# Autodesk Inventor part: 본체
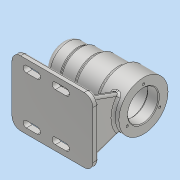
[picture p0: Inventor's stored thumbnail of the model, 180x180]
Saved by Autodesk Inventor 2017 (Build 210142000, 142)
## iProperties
Part Number: 본체
Material: 알루미늄 6061
Document SubType Name: Modeling
Designer: MRC
Density: 2.7 g/cm^3
Appearance: 알루미늄 - 평지
Mass: 694.197 g
Surface Area: 698.877 cm^2
Volume: 257.11 cm^3
Author: MRC
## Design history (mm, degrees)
sketch "스케치1"
  geometry: L1 (0, 0)-(-112, 0); L2 (0, 0)-(0, 34); L3 (0, 34)-(-32, 34); L4 (-32, 34)-(-32, 30); L5 (-32, 30)-(-66, 30); L6 (-66, 30)-(-66, 27); L7 (-66, 27)-(-88, 27); L8 (-88, 27)-(-88, 25); L9 (-88, 25)-(-112, 25); L10 (-112, 25)-(-112, 0); L11 (0, 21)-(-15, 21); L12 (-15, 21)-(-15, 24); L13 (-15, 24)-(-69, 24); L14 (-69, 24)-(-69, 21); L15 (-69, 21)-(-81, 21); L16 (-81, 21)-(-81, 17.5); L17 (-81, 17.5)-(-99, 17.5); L18 (-99, 17.5)-(-99, 16); L19 (-99, 16)-(-103, 16); L20 (-103, 16)-(-103, 10.5); L21 (-103, 10.5)-(-106, 10.5); L22 (-106, 10.5)-(-106, 0)
  constraints: 44 end point, 15 perpendicular, 3 vertical, 2 horizontal, 2 point on line, 1 parallel
  dimensions: "d0" = 112 distance of L1.start L1.end; "d1" = 24 distance between parallel lines of L8 L10; "d2" = 46 distance between parallel lines of L6 L10; "d3" = 80 distance between parallel lines of L4 L10; "d4" = 68 diameter of L3 L1; "d5" = 60 diameter of L5 L1; "d6" = 54 diameter of L7 L1; "d7" = 50 diameter of L9 L1; "d8" = 15 distance of L11.start L11.end; "d9" = 54 distance of L12.end L13.end; "d10" = 12 distance of L14.end L15.end; "d11" = 18 distance of L16.end L17.end; "d12" = 4 distance of L18.end L19.end; "d13" = 3 distance of L20.end L21.end; "d14" = 42 diameter of L11 L1; "d15" = 48 diameter of L13 L1; "d16" = 42 diameter of L15 L1; "d17" = 35 diameter of L17 L1; "d18" = 32 diameter of L19 L1; "d19" = 21 diameter of L21 L1
revolve "회전1" sketch "스케치1" stored, may be unused: angle "d20" = 90 deg
fillet "모깎기1" dims "d21" = 0.3
fillet "모깎기2" dims "d22" = 3
chamfer "모따기1" distance "d23" = 1; stored, may be unused: second distance "d24" = 2, angle "d25" = 45 deg
fillet "모깎기3" dims "d26" = 8
fillet "모깎기4" dims "d27" = 3
sketch "스케치2"
  geometry: L1 (0, 0)-(13, 22.517); L2 (0, 0)-(26, 0); C1 r 22 at (0, 0) reference; 1 further point
  constraints: 4 end point, 1 coincident, 1 equal length, 1 horizontal
  dimensions: "d28" = 26 distance of L1.start L1.end; "d29" = 60 deg angle of L2 L1
hole "구멍1" sketch "스케치2" at (13, 22.517) diameter "d30" = 3.242; stored, may be unused: countersink angle "d34" = 90 deg, drill point angle "d36" = 118 deg; dims "d31" = 8, "d32" = 4, "d33" = 2, "d35" = 11
node "작업 평면1"
sketch "스케치3"
  geometry: L1 (112, -45)-(0, -45); L2 (0, -45)-(0, 45); L3 (0, 45)-(112, 45); L4 (112, 45)-(112, -45); 2 further points
  constraints: 8 end point, 2 parallel, 1 coincident, 1 horizontal, 1 midpoint, 1 perpendicular
  dimensions: "d41" = 112 distance of L2.end L3.end; "d42" = 90 distance of L1.end L2.end
extrude "돌출1" join sketch "스케치3" distance "d43" = 8; taper "d44" = 0 deg
fillet "모깎기5" dims "d45" = 12
node "작업 평면2"
sketch "스케치4"
  geometry: L1 (56.409, 45.342)-(70, 8); L2 (9.591, 45.342)-(-4, 8); L3 (66, 8)-(78, 8) reference; L4 (-12, 8)-(0, 8) reference; L5 (78, 0)-(78, 8) reference; L6 (-12, 8)-(-12, 0) reference; L7 (-4, 8)-(70, 8); A1 r 34 centre (33, 70) between (9.591, 45.342) and (56.409, 45.342) reference; 1 further point
  constraints: 6 end point, 2 point on circle, 2 point on line, 1 horizontal
  dimensions: "d47" = 8 distance from line of L5 L1.end; "d48" = 8 distance from line of L6 L2.end; "d49" = 110 deg angle of L4 L2; "d50" = 110 deg angle of L3 L1
extrude "돌출2" join sketch "스케치4" distance "d51" = 8; taper "d52" = 0 deg
sketch "스케치5"
  geometry: L1 (-78.717, -38.552)-(-85, -62); L2 (-12, -62)-(-100, -62) reference; L3 (-8, -62)-(-8, -24.658) reference; 1 further point
  constraints: 2 end point, 1 point on line
  dimensions: "d53" = 77 distance from line of L3 L1.end; "d54" = 105 deg angle of L2 L1
feature "리브1" sketch "스케치5" dims "d55" = 1, "d56" = 8, "d57" = 0, "d58" = 0, "d59" = 1, "d60" = 1
fillet "모깎기6" dims "d61" = 3
fillet "모깎기7" dims "d62" = 3
sketch "스케치6"
  geometry: L1 (-112, 33)-(-112, -33) reference; L2 (-92, -33)-(-77, -33); L3 (-92, -37.5)-(-77, -37.5); L4 (-77, -28.5)-(-92, -28.5); L5 (-52, -33)-(-37, -33); L6 (-52, -37.5)-(-37, -37.5); L7 (-37, -28.5)-(-52, -28.5); A1 r 4.5 centre (-92, -33) between (-92, -28.5) and (-92, -37.5); A2 r 4.5 centre (-77, -33) between (-77, -37.5) and (-77, -28.5); A3 r 4.5 centre (-52, -33) between (-52, -28.5) and (-52, -37.5); A4 r 4.5 centre (-37, -33) between (-37, -37.5) and (-37, -28.5); 3 further points
  constraints: 16 end point, 8 point on circle, 8 tangent, 4 centre point, 2 midpoint, 2 parallel, 2 point on line, 1 horizontal
  dimensions: "d63" = 15 distance of L2.start L2.end; "d64" = 9 diameter of A2; "d65" = 15 distance of L5.start L5.end; "d66" = 9 diameter of A4; "d67" = 33 vertical distance of L2.start point (0, 0); "d68" = 20 distance from line of L1 L2.start; "d69" = 25 distance of L5.start L2.end
extrude "돌출3" cut sketch "스케치6" stored distance "d70" = 8; taper "d71" = 0 deg
fillet "모깎기8" dims "d72" = 3
sketch "스케치7"
  geometry: L1 (-112, 33)-(-112, -33) reference; 2 further points
  constraints: 1 horizontal alignment, 1 other
  dimensions: "d73" = 12 distance from line of L1 point (-100, 0)
feature "엠보싱1" sketch "스케치7" dims "d0" = 112, "d1" = 24, "d2" = 46, "d3" = 80, "d4" = 68, "d5" = 60, "d6" = 54, "d7" = 50, "d8" = 15, "d9" = 54, "d10" = 12, "d11" = 18, "d12" = 4, "d13" = 3, "d14" = 42, "d15" = 48, "d16" = 42, "d17" = 35, "d18" = 32, "d19" = 21, "d74" = 0.5, "d75" = 0
node "솔리드1"
pattern_circular "원형 패턴1" dims angle "d38" = 360 deg
mirror "미러1"
other parameters: "d46" = -8
